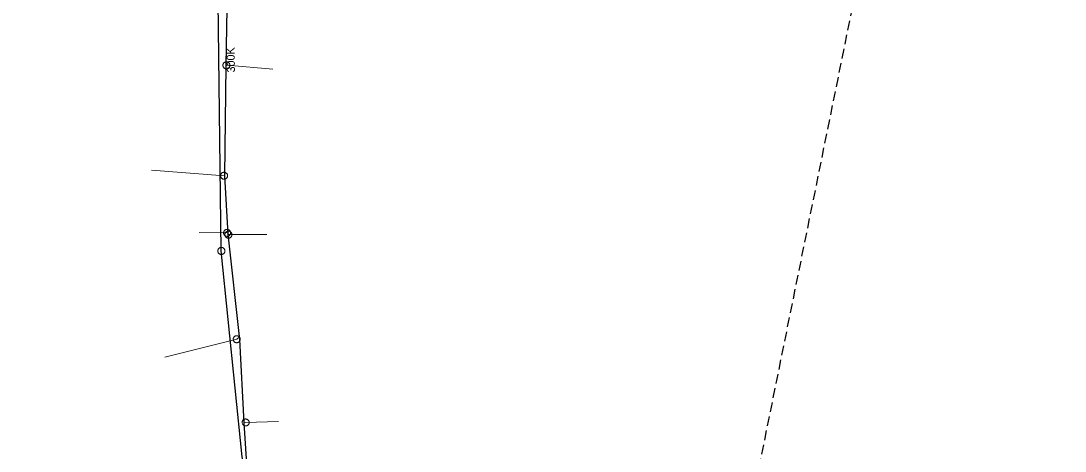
# Model space of a CAD drawing. Extents: x -741806 to -738704, y -1059275 to -1055387.
# Drawn here: x -740170.7 to -740040.2, y -1056821.5 to -1056767.8 of the extents above; entities that cross this region are included whole.
import ezdxf

# ---------------------------------------------------------------- set-up
doc = ezdxf.new("R2010")
doc.units = 0
doc.header["$LTSCALE"] = 0.4
doc.linetypes.add('MEDIUM_DASHED', pattern=[4.5, 3, -1.5])
for name, color, linetype, lineweight in [('2', 7, 'Continuous', 25), ('21', 7, 'Continuous', 13), ('3', 7, 'Continuous', 13), ('51', 7, 'Continuous', 13), ('52', 7, 'Continuous', 25), ('63', 7, 'MEDIUM_DASHED', 25)]:
    doc.layers.add(name, color=color, linetype=linetype, lineweight=lineweight)
doc.layers.add('5', color=7, linetype='Continuous')

msp = doc.modelspace()

# ---------------------------------------------------------------- linework, layer by layer
at = {"layer": '2'}
msp.add_lwpolyline([(-740138.59, -1056847.639), (-740143.066, -1056822.229), (-740145.66, -1056796.55), (-740146.28, -1056748.03), (-740128.43, -1056723.98)], dxfattribs=at)
at = {"layer": '21'}
msp.add_line((-740145.25, -1056787.189), (-740154.364, -1056786.483), dxfattribs=at)
for points in [[(-740145.093, -1056773.368), (-740144.942, -1056773.372), (-740139.206, -1056773.865)], [(-740144.855, -1056794.283), (-740144.94, -1056794.29), (-740148.436, -1056794.233)], [(-740144.836, -1056794.54), (-740144.78, -1056794.51), (-740144.5, -1056794.486), (-740139.969, -1056794.487)], [(-740143.429, -1056807.314), (-740143.739, -1056807.568), (-740152.714, -1056809.815)], [(-740142.849, -1056818.006), (-740142.62, -1056817.948), (-740138.528, -1056817.818)]]:
    msp.add_lwpolyline(points, dxfattribs=at)
at = {"layer": '3'}
msp.add_lwpolyline([(-740145.703, -1056796.114), (-740145.747, -1056796.121), (-740145.792, -1056796.133), (-740145.835, -1056796.149), (-740145.875, -1056796.169), (-740145.914, -1056796.194), (-740145.95, -1056796.223), (-740145.982, -1056796.255), (-740146.012, -1056796.291), (-740146.036, -1056796.329), (-740146.057, -1056796.37), (-740146.074, -1056796.412), (-740146.086, -1056796.457), (-740146.093, -1056796.502), (-740146.096, -1056796.547), (-740146.094, -1056796.593), (-740146.087, -1056796.639), (-740146.075, -1056796.683), (-740146.059, -1056796.726), (-740146.038, -1056796.767), (-740146.013, -1056796.805), (-740145.984, -1056796.841), (-740145.953, -1056796.873), (-740145.917, -1056796.902), (-740145.879, -1056796.927), (-740145.838, -1056796.948), (-740145.795, -1056796.964), (-740145.752, -1056796.977), (-740145.706, -1056796.984), (-740145.66, -1056796.987), (-740145.614, -1056796.984), (-740145.57, -1056796.978), (-740145.525, -1056796.966), (-740145.482, -1056796.95), (-740145.441, -1056796.928), (-740145.403, -1056796.905), (-740145.367, -1056796.876), (-740145.335, -1056796.843), (-740145.305, -1056796.807), (-740145.281, -1056796.77), (-740145.26, -1056796.729), (-740145.243, -1056796.686), (-740145.231, -1056796.642), (-740145.223, -1056796.597), (-740145.221, -1056796.551), (-740145.223, -1056796.505), (-740145.23, -1056796.46), (-740145.241, -1056796.416), (-740145.258, -1056796.373), (-740145.279, -1056796.332), (-740145.304, -1056796.293), (-740145.333, -1056796.258), (-740145.364, -1056796.225), (-740145.4, -1056796.197), (-740145.438, -1056796.171), (-740145.479, -1056796.15), (-740145.522, -1056796.134), (-740145.566, -1056796.122), (-740145.611, -1056796.114), (-740145.657, -1056796.112), (-740145.702, -1056796.114)], dxfattribs=at)
at = {"layer": '51'}
for points in [[(-740144.593, -1056773.393), (-740144.593, -1056773.348), (-740144.599, -1056773.302), (-740144.61, -1056773.257), (-740144.624, -1056773.214), (-740144.644, -1056773.173), (-740144.668, -1056773.133), (-740144.696, -1056773.097), (-740144.727, -1056773.063), (-740144.762, -1056773.034), (-740144.799, -1056773.008), (-740144.839, -1056772.986), (-740144.882, -1056772.967), (-740144.925, -1056772.954), (-740144.97, -1056772.946), (-740145.016, -1056772.942), (-740145.062, -1056772.943), (-740145.107, -1056772.948), (-740145.152, -1056772.959), (-740145.195, -1056772.975), (-740145.237, -1056772.994), (-740145.275, -1056773.018), (-740145.312, -1056773.045), (-740145.345, -1056773.077), (-740145.375, -1056773.111), (-740145.402, -1056773.149), (-740145.424, -1056773.19), (-740145.441, -1056773.231), (-740145.455, -1056773.276), (-740145.463, -1056773.321), (-740145.467, -1056773.366), (-740145.466, -1056773.411), (-740145.46, -1056773.457), (-740145.45, -1056773.502), (-740145.435, -1056773.545), (-740145.415, -1056773.586), (-740145.391, -1056773.626), (-740145.363, -1056773.662), (-740145.332, -1056773.696), (-740145.297, -1056773.725), (-740145.26, -1056773.751), (-740145.22, -1056773.773), (-740145.177, -1056773.792), (-740145.134, -1056773.804), (-740145.089, -1056773.813), (-740145.043, -1056773.817), (-740144.997, -1056773.816), (-740144.952, -1056773.81), (-740144.908, -1056773.8), (-740144.864, -1056773.784), (-740144.822, -1056773.765), (-740144.784, -1056773.741), (-740144.747, -1056773.714), (-740144.714, -1056773.682), (-740144.684, -1056773.648), (-740144.657, -1056773.61), (-740144.635, -1056773.569), (-740144.618, -1056773.528), (-740144.605, -1056773.483), (-740144.596, -1056773.438), (-740144.593, -1056773.394)], [(-740145.755, -1056787.134), (-740145.757, -1056787.179), (-740145.753, -1056787.225), (-740145.745, -1056787.271), (-740145.732, -1056787.314), (-740145.714, -1056787.356), (-740145.692, -1056787.397), (-740145.666, -1056787.434), (-740145.637, -1056787.469), (-740145.603, -1056787.5), (-740145.567, -1056787.528), (-740145.528, -1056787.552), (-740145.486, -1056787.572), (-740145.443, -1056787.588), (-740145.399, -1056787.598), (-740145.353, -1056787.604), (-740145.307, -1056787.605), (-740145.262, -1056787.602), (-740145.217, -1056787.593), (-740145.173, -1056787.58), (-740145.13, -1056787.562), (-740145.09, -1056787.54), (-740145.052, -1056787.515), (-740145.018, -1056787.484), (-740144.986, -1056787.452), (-740144.958, -1056787.415), (-740144.934, -1056787.375), (-740144.915, -1056787.335), (-740144.9, -1056787.291), (-740144.889, -1056787.246), (-740144.883, -1056787.201), (-740144.882, -1056787.156), (-740144.886, -1056787.11), (-740144.894, -1056787.064), (-740144.907, -1056787.021), (-740144.925, -1056786.979), (-740144.947, -1056786.938), (-740144.973, -1056786.901), (-740145.002, -1056786.866), (-740145.036, -1056786.835), (-740145.072, -1056786.807), (-740145.111, -1056786.783), (-740145.153, -1056786.763), (-740145.196, -1056786.748), (-740145.24, -1056786.737), (-740145.286, -1056786.731), (-740145.332, -1056786.73), (-740145.377, -1056786.734), (-740145.422, -1056786.742), (-740145.466, -1056786.755), (-740145.509, -1056786.773), (-740145.548, -1056786.795), (-740145.586, -1056786.82), (-740145.621, -1056786.851), (-740145.653, -1056786.883), (-740145.68, -1056786.92), (-740145.705, -1056786.96), (-740145.724, -1056787), (-740145.739, -1056787.044), (-740145.75, -1056787.089), (-740145.755, -1056787.133)], [(-740145.375, -1056794.325), (-740145.369, -1056794.369), (-740145.359, -1056794.413), (-740145.343, -1056794.457), (-740145.324, -1056794.498), (-740145.3, -1056794.537), (-740145.271, -1056794.574), (-740145.24, -1056794.606), (-740145.205, -1056794.637), (-740145.167, -1056794.662), (-740145.127, -1056794.684), (-740145.085, -1056794.701), (-740145.04, -1056794.715), (-740144.995, -1056794.723), (-740144.95, -1056794.726), (-740144.904, -1056794.725), (-740144.858, -1056794.719), (-740144.814, -1056794.708), (-740144.771, -1056794.693), (-740144.73, -1056794.672), (-740144.691, -1056794.648), (-740144.655, -1056794.62), (-740144.621, -1056794.589), (-740144.592, -1056794.554), (-740144.566, -1056794.516), (-740144.544, -1056794.475), (-740144.526, -1056794.433), (-740144.514, -1056794.39), (-740144.506, -1056794.344), (-740144.502, -1056794.298), (-740144.503, -1056794.252), (-740144.51, -1056794.208), (-740144.52, -1056794.164), (-740144.536, -1056794.12), (-740144.555, -1056794.079), (-740144.58, -1056794.04), (-740144.608, -1056794.003), (-740144.639, -1056793.971), (-740144.674, -1056793.94), (-740144.712, -1056793.915), (-740144.752, -1056793.893), (-740144.795, -1056793.876), (-740144.839, -1056793.862), (-740144.884, -1056793.855), (-740144.929, -1056793.851), (-740144.975, -1056793.852), (-740145.021, -1056793.858), (-740145.065, -1056793.87), (-740145.108, -1056793.884), (-740145.149, -1056793.905), (-740145.189, -1056793.929), (-740145.224, -1056793.957), (-740145.258, -1056793.988), (-740145.287, -1056794.023), (-740145.313, -1056794.061), (-740145.335, -1056794.102), (-740145.353, -1056794.144), (-740145.365, -1056794.187), (-740145.374, -1056794.233), (-740145.377, -1056794.279), (-740145.375, -1056794.324)], [(-740144.394, -1056794.303), (-740144.418, -1056794.264), (-740144.445, -1056794.228), (-740144.477, -1056794.194), (-740144.511, -1056794.165), (-740144.549, -1056794.138), (-740144.589, -1056794.116), (-740144.631, -1056794.099), (-740144.675, -1056794.085), (-740144.72, -1056794.077), (-740144.766, -1056794.073), (-740144.812, -1056794.074), (-740144.858, -1056794.08), (-740144.902, -1056794.09), (-740144.945, -1056794.105), (-740144.986, -1056794.125), (-740145.026, -1056794.149), (-740145.062, -1056794.176), (-740145.095, -1056794.208), (-740145.125, -1056794.243), (-740145.151, -1056794.281), (-740145.173, -1056794.321), (-740145.191, -1056794.363), (-740145.204, -1056794.407), (-740145.213, -1056794.451), (-740145.216, -1056794.498), (-740145.215, -1056794.544), (-740145.21, -1056794.588), (-740145.199, -1056794.634), (-740145.184, -1056794.676), (-740145.164, -1056794.718), (-740145.141, -1056794.757), (-740145.113, -1056794.793), (-740145.081, -1056794.827), (-740145.047, -1056794.856), (-740145.009, -1056794.882), (-740144.969, -1056794.905), (-740144.927, -1056794.922), (-740144.883, -1056794.936), (-740144.838, -1056794.943), (-740144.792, -1056794.947), (-740144.746, -1056794.947), (-740144.701, -1056794.941), (-740144.657, -1056794.93), (-740144.613, -1056794.916), (-740144.572, -1056794.896), (-740144.532, -1056794.872), (-740144.496, -1056794.844), (-740144.463, -1056794.813), (-740144.433, -1056794.778), (-740144.407, -1056794.74), (-740144.385, -1056794.7), (-740144.367, -1056794.658), (-740144.354, -1056794.614), (-740144.345, -1056794.569), (-740144.342, -1056794.523), (-740144.343, -1056794.477), (-740144.348, -1056794.433), (-740144.359, -1056794.387), (-740144.374, -1056794.344), (-740144.394, -1056794.304)], [(-740144.076, -1056807.845), (-740144.046, -1056807.878), (-740144.012, -1056807.909), (-740143.974, -1056807.936), (-740143.935, -1056807.958), (-740143.893, -1056807.976), (-740143.849, -1056807.991), (-740143.804, -1056807.999), (-740143.758, -1056808.004), (-740143.713, -1056808.003), (-740143.668, -1056807.998), (-740143.623, -1056807.988), (-740143.579, -1056807.974), (-740143.537, -1056807.955), (-740143.498, -1056807.932), (-740143.461, -1056807.905), (-740143.427, -1056807.874), (-740143.397, -1056807.84), (-740143.37, -1056807.803), (-740143.348, -1056807.762), (-740143.33, -1056807.72), (-740143.316, -1056807.676), (-740143.306, -1056807.632), (-740143.302, -1056807.586), (-740143.302, -1056807.541), (-740143.308, -1056807.495), (-740143.317, -1056807.45), (-740143.332, -1056807.407), (-740143.351, -1056807.365), (-740143.374, -1056807.325), (-740143.401, -1056807.288), (-740143.432, -1056807.255), (-740143.466, -1056807.225), (-740143.504, -1056807.198), (-740143.543, -1056807.175), (-740143.585, -1056807.157), (-740143.629, -1056807.143), (-740143.674, -1056807.134), (-740143.72, -1056807.129), (-740143.765, -1056807.13), (-740143.811, -1056807.135), (-740143.856, -1056807.145), (-740143.9, -1056807.159), (-740143.941, -1056807.179), (-740143.98, -1056807.201), (-740144.017, -1056807.229), (-740144.051, -1056807.26), (-740144.081, -1056807.294), (-740144.108, -1056807.331), (-740144.13, -1056807.371), (-740144.149, -1056807.414), (-740144.162, -1056807.457), (-740144.172, -1056807.502), (-740144.176, -1056807.547), (-740144.176, -1056807.593), (-740144.171, -1056807.639), (-740144.161, -1056807.684), (-740144.146, -1056807.726), (-740144.127, -1056807.769), (-740144.104, -1056807.808), (-740144.077, -1056807.844)], [(-740142.196, -1056817.84), (-740142.209, -1056817.797), (-740142.227, -1056817.755), (-740142.249, -1056817.715), (-740142.275, -1056817.678), (-740142.306, -1056817.643), (-740142.34, -1056817.612), (-740142.376, -1056817.585), (-740142.416, -1056817.561), (-740142.457, -1056817.543), (-740142.5, -1056817.528), (-740142.545, -1056817.517), (-740142.591, -1056817.512), (-740142.637, -1056817.511), (-740142.682, -1056817.515), (-740142.727, -1056817.524), (-740142.771, -1056817.538), (-740142.813, -1056817.556), (-740142.853, -1056817.578), (-740142.89, -1056817.605), (-740142.925, -1056817.636), (-740142.955, -1056817.669), (-740142.983, -1056817.705), (-740143.006, -1056817.745), (-740143.026, -1056817.786), (-740143.04, -1056817.83), (-740143.051, -1056817.875), (-740143.056, -1056817.92), (-740143.056, -1056817.966), (-740143.052, -1056818.012), (-740143.044, -1056818.057), (-740143.03, -1056818.1), (-740143.012, -1056818.142), (-740142.989, -1056818.182), (-740142.963, -1056818.219), (-740142.933, -1056818.254), (-740142.899, -1056818.285), (-740142.862, -1056818.312), (-740142.823, -1056818.336), (-740142.781, -1056818.354), (-740142.738, -1056818.369), (-740142.693, -1056818.38), (-740142.647, -1056818.385), (-740142.602, -1056818.385), (-740142.556, -1056818.382), (-740142.511, -1056818.372), (-740142.467, -1056818.359), (-740142.426, -1056818.34), (-740142.386, -1056818.319), (-740142.348, -1056818.292), (-740142.314, -1056818.261), (-740142.283, -1056818.228), (-740142.255, -1056818.192), (-740142.232, -1056818.152), (-740142.213, -1056818.111), (-740142.198, -1056818.067), (-740142.188, -1056818.022), (-740142.183, -1056817.977), (-740142.182, -1056817.931), (-740142.186, -1056817.885), (-740142.196, -1056817.841)]]:
    msp.add_lwpolyline(points, dxfattribs=at)
at = {"layer": '52'}
msp.add_lwpolyline([(-740141.241, -1056737.757), (-740144.317, -1056746.739), (-740144.39, -1056748.904), (-740144.794, -1056756.72), (-740145.094, -1056773.397), (-740145.25, -1056787.189), (-740144.846, -1056794.452), (-740143.399, -1056807.584), (-740142.849, -1056818.006), (-740141.831, -1056833.438), (-740140.785, -1056837.31), (-740139.377, -1056847.807), (-740136.706, -1056857.977)], dxfattribs=at)
at = {"layer": '63'}
msp.add_lwpolyline([(-738703.895, -1055774.865), (-739961.423, -1056247.456), (-740265.345, -1057742.853)], dxfattribs=at)

# ---------------------------------------------------------------- texts
at = {"layer": '5'}
msp.add_text('300K', height=1, rotation=91, dxfattribs=at).set_placement((-740143.958, -1056774.264))

doc.saveas('drawing.dxf')
